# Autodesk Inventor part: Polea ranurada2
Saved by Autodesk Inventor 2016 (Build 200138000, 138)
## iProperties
Created: 2016-06
Part Number: Polea ranurada2
Material: Steel
Document SubType Name: Modeling
Designer: adm
Mass: 701.241 g
Surface Area: 207.725 cm^2
Volume: 89.33 cm^3
Density: 7.85 g/cm^3
Appearance: Steel
CustomPartVersion: 1
Author: adm
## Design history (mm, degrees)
sketch "Boceto principal"
  geometry: L1 (0, 19.05)-(43.815, 19.05); L2 (43.815, 19.05)-(43.815, 15.804); L3 (43.815, 15.804)-(32.131, 12.232); L4 (32.131, 12.232)-(32.131, 6.818); L5 (32.131, 6.818)-(43.815, 3.246); L6 (43.815, 3.246)-(43.815, 0); L7 (43.815, 0)-(0, 0); L8 (40.64, 14.834)-(40.64, 4.216); L9 (32.131, 9.525)-(40.64, 9.525); L10 (43.815, 15.804)-(43.815, 3.246); L11 (0, -4)-(0, 24) reference; L12 (0, 0)-(0, 19.05)
  constraints: 22 end point, 5 perpendicular, 2 collinear, 2 midpoint, 2 point on line, 1 parallel
  dimensions: "d0" = 10.6172 distance of L8.start L8.end (= da_Bw); "d1" = 34 deg angle of L3 L5 (= da_Alfa); "d2" = 3.175 distance between parallel lines of L2 L8 (= da_c); "d6" = 19.05 distance between parallel lines of L7 L1 (computed from d5, da_ng, da_Sg); "d21" = 81.28 diameter of L8 L11 (= da_Dw); "d25" = 11.684 distance between parallel lines of L4 L10 (= da_Hd); "d27" = 9.525 distance between parallel lines of L7 L9 (= da_Se)
node "Plano de correa"
revolve "Cuerpo" stored, may be unused: angle "d7" = 90 deg
revolve "Para ranuras" stored, may be unused: angle "d15" = 90 deg
fillet "Empalme externo" dims "d8" = 0 (computed from da_r1), "d10" = 0, "da_r1" = 0 [user parameter; used in 1 equation term]
fillet "Empalme interno" dims "d9" = 0 (computed from da_r2), "d11" = 0, "da_r2" = 0 [user parameter; used in 1 equation term]
pattern_linear "Patrón para ranuras" dims "d18" = 15.875 (= da_Sg)
body "Solid1"
other parameters: "d5" = 9.525 (= da_Se), "da_Bw" = 10.6172 [user parameter; used in 1 equation term], "da_Alfa" = 34 deg [user parameter; used in 1 equation term], "da_c" = 3.175 [user parameter; used in 1 equation term], "da_Dw" = 81.28 [user parameter; used in 1 equation term], "da_Hd" = 11.684 [user parameter; used in 1 equation term], "da_Se" = 9.525 [user parameter; used in 2 equation terms], "da_Sg" = 15.875 [user parameter; used in 2 equation terms], "d24" = 0, "d26" = 0
